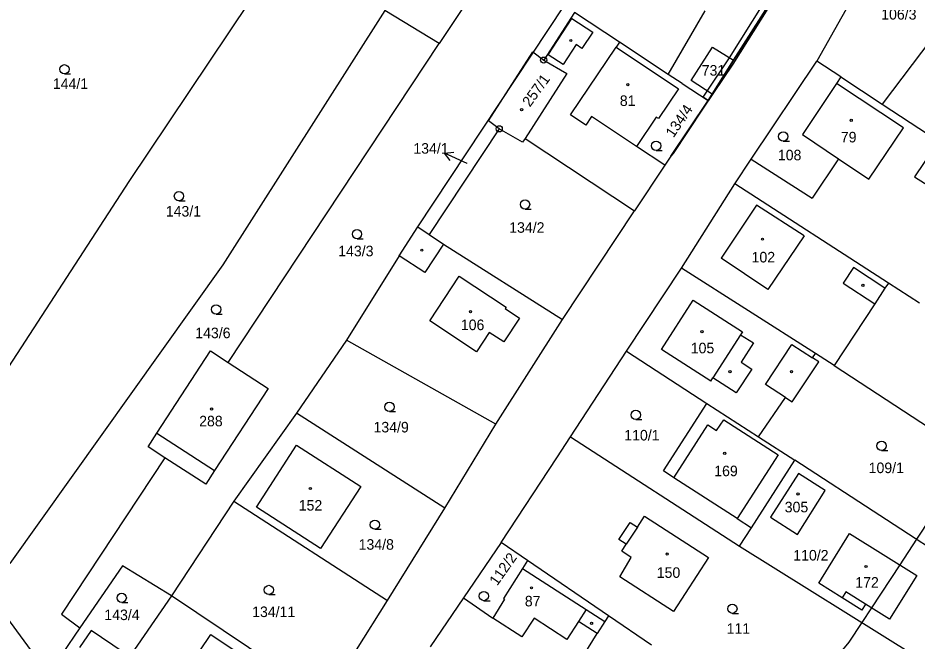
# Model space of a CAD drawing. Extents: x -747333 to -745433, y -1133152 to -1130600.
# Drawn here: x -746336.6 to -746191.7, y -1131743.1 to -1131642.6 of the extents above; entities that cross this region are included whole.
import ezdxf

# ---------------------------------------------------------------- set-up
doc = ezdxf.new("R2010")
doc.units = 0
for name, color, linetype in [('Vrstva 1', 7, 'Continuous'), ('Vrstva 16', 7, 'Continuous'), ('Vrstva 18', 7, 'Continuous'), ('Vrstva 19', 7, 'Continuous'), ('Vrstva 24', 7, 'Continuous'), ('Vrstva 25', 7, 'Continuous'), ('Vrstva 3', 7, 'Continuous'), ('Vrstva 30', 7, 'Continuous'), ('Vrstva 37', 7, 'Continuous'), ('Vrstva 4', 7, 'Continuous'), ('Vrstva 52', 7, 'Continuous'), ('Vrstva 6', 7, 'Continuous')]:
    doc.layers.add(name, color=color, linetype=linetype)

msp = doc.modelspace()

# ---------------------------------------------------------------- linework, layer by layer
at = {"layer": 'Vrstva 1'}
for p, q in [((-746246.92, -1131641.69), (-746251.87, -1131649.36)), ((-746302.76, -1131698.11), (-746268.75, -1131646.7)), ((-746251.87, -1131649.36), (-746248.14, -1131651.53)), ((-746248.14, -1131651.53), (-746254.86, -1131661.98)), ((-746259.04, -1131660.44), (-746270.36, -1131677.49)), ((-746255.27, -1131662.62), (-746259.04, -1131660.44)), ((-746254.86, -1131661.98), (-746255.27, -1131662.62)), ((-746254.86, -1131661.98), (-746237.23, -1131673.69)), ((-746314.24, -1131709.54), (-746305.6, -1131696.26)), ((-746305.6, -1131696.26), (-746302.76, -1131698.11)), ((-746208.52, -1131697.37), (-746208.05, -1131696.69)), ((-746302.76, -1131698.11), (-746296.31, -1131702.3)), ((-746211.79, -1131704.5), (-746207.53, -1131698.01)), ((-746207.53, -1131698.01), (-746208.52, -1131697.37)), ((-746296.31, -1131702.3), (-746304.95, -1131715.57)), ((-746217.23, -1131710.1), (-746212.9, -1131703.77)), ((-746212.9, -1131703.77), (-746211.79, -1131704.5)), ((-746315.66, -1131711.72), (-746314.24, -1131709.54)), ((-746312.93, -1131713.49), (-746315.66, -1131711.72)), ((-746312.93, -1131713.49), (-746329.64, -1131738.75)), ((-746306.37, -1131717.75), (-746312.93, -1131713.49)), ((-746304.95, -1131715.57), (-746306.37, -1131717.75)), ((-746210.77, -1131716.05), (-746215.29, -1131723.08)), ((-746206.49, -1131718.76), (-746210.77, -1131716.05)), ((-746210.97, -1131725.86), (-746206.49, -1131718.76)), ((-746215.29, -1131723.08), (-746210.97, -1131725.86)), ((-746324.84, -1131741.34), (-746326.74, -1131744.1)), ((-746319.67, -1131744.87), (-746324.84, -1131741.34))]:
    msp.add_line(p, q, dxfattribs=at)
for points in [[(-746256.41, -1131628.18), (-746268.75, -1131646.7)], [(-746221.25, -1131649.38), (-746209.49, -1131630.87)], [(-746178.11, -1131631.02), (-746197.29, -1131656.44)], [(-746200.96, -1131637.27), (-746207.82, -1131649.53)], [(-746277.47, -1131641.33), (-746303.62, -1131682.4)], [(-746268.75, -1131646.7), (-746277.47, -1131641.33)], [(-746272.19, -1131676.27), (-746248.59, -1131640.59)], [(-746239.66, -1131646.47), (-746246.92, -1131641.69)], [(-746231.78, -1131651.66), (-746225.82, -1131641.41)], [(-746239.66, -1131646.47), (-746240.2, -1131647.27)], [(-746240.2, -1131647.27), (-746230.15, -1131654.01)], [(-746231.78, -1131651.66), (-746239.66, -1131646.47)], [(-746228.08, -1131652.63), (-746224.65, -1131647.29)], [(-746224.65, -1131647.29), (-746221.25, -1131649.38)], [(-746259.04, -1131660.44), (-746260.76, -1131659.13), (-746253.62, -1131648.01), (-746251.87, -1131649.36)], [(-746224.73, -1131654.87), (-746221.25, -1131649.38)], [(-746218.4, -1131665.32), (-746207.82, -1131649.53)], [(-746203.97, -1131652.06), (-746207.82, -1131649.53)], [(-746229.55, -1131653.12), (-746231.78, -1131651.66)], [(-746229.55, -1131653.12), (-746225.37, -1131655.87)], [(-746224.73, -1131654.87), (-746228.08, -1131652.63)], [(-746204.68, -1131653.13), (-746210.15, -1131661.38)], [(-746203.97, -1131652.06), (-746204.68, -1131653.13)], [(-746203.97, -1131652.06), (-746197.29, -1131656.44)], [(-746230.15, -1131654.01), (-746233.36, -1131658.8)], [(-746225.37, -1131655.87), (-746224.73, -1131654.87)], [(-746225.37, -1131655.87), (-746232.33, -1131666.33)], [(-746197.29, -1131656.44), (-746178.01, -1131669.1)], [(-746233.75, -1131658.54), (-746236.91, -1131663.29)], [(-746233.36, -1131658.8), (-746233.75, -1131658.54)], [(-746210.15, -1131661.38), (-746204.34, -1131665.28)], [(-746232.33, -1131666.33), (-746236.91, -1131663.29)], [(-746232.33, -1131666.33), (-746237.23, -1131673.69)], [(-746221.07, -1131669.31), (-746218.4, -1131665.32)], [(-746218.4, -1131665.32), (-746208.6, -1131671.63)], [(-746204.34, -1131665.28), (-746208.6, -1131671.63)], [(-746229.64, -1131682.94), (-746221.07, -1131669.31)], [(-746196.29, -1131685.32), (-746221.07, -1131669.31)], [(-746248.85, -1131691.18), (-746237.23, -1131673.69)], [(-746275.18, -1131680.92), (-746272.19, -1131676.27)], [(-746272.19, -1131676.27), (-746270.36, -1131677.49)], [(-746270.36, -1131677.49), (-746268.02, -1131679.05)], [(-746268.02, -1131679.05), (-746248.85, -1131691.18)], [(-746275.18, -1131680.92), (-746283.65, -1131694.51)], [(-746303.62, -1131682.4), (-746337.96, -1131730.57)], [(-746238.54, -1131696.32), (-746229.64, -1131682.94)], [(-746208.05, -1131696.69), (-746229.64, -1131682.94)], [(-746196.29, -1131685.32), (-746196.84, -1131686.16)], [(-746191.3, -1131688.55), (-746196.29, -1131685.32)], [(-746196.84, -1131686.16), (-746198.48, -1131688.67)], [(-746198.48, -1131688.67), (-746205.01, -1131698.62)], [(-746259.58, -1131708.06), (-746248.85, -1131691.18)], [(-746283.65, -1131694.51), (-746291.7, -1131706.32)], [(-746259.58, -1131708.06), (-746283.65, -1131694.51)], [(-746247.57, -1131710.13), (-746238.54, -1131696.32)], [(-746238.54, -1131696.32), (-746225.54, -1131704.73)], [(-746205.01, -1131698.62), (-746208.05, -1131696.69)], [(-746205.01, -1131698.62), (-746175.84, -1131717.7)], [(-746232.57, -1131715.63), (-746225.54, -1131704.73)], [(-746225.54, -1131704.73), (-746217.23, -1131710.1)], [(-746291.7, -1131706.32), (-746301.83, -1131720.48)], [(-746267.83, -1131721.62), (-746291.7, -1131706.32)], [(-746267.83, -1131721.62), (-746259.58, -1131708.06)], [(-746249.77, -1131713.5), (-746247.57, -1131710.13)], [(-746247.57, -1131710.13), (-746220.28, -1131727.78)], [(-746217.23, -1131710.1), (-746211.35, -1131713.91)], [(-746298.18, -1131721.44), (-746291.72, -1131711.44)], [(-746291.72, -1131711.44), (-746281.34, -1131718.15)], [(-746258.71, -1131727.17), (-746249.77, -1131713.5)], [(-746218.35, -1131724.78), (-746211.35, -1131713.91)], [(-746183.97, -1131731.72), (-746211.35, -1131713.91)], [(-746230.88, -1131716.72), (-746232.57, -1131715.63)], [(-746220.68, -1131723.28), (-746230.88, -1131716.72)], [(-746281.34, -1131718.15), (-746287.86, -1131728.15)], [(-746301.83, -1131720.48), (-746311.89, -1131735.77)], [(-746301.83, -1131720.48), (-746277.08, -1131736.51)], [(-746287.86, -1131728.15), (-746298.18, -1131721.44)], [(-746277.08, -1131736.51), (-746267.83, -1131721.62)], [(-746236.77, -1131724.69), (-746235.61, -1131722.9)], [(-746235.61, -1131722.9), (-746225.29, -1131729.6)], [(-746239.73, -1131726.67), (-746237.95, -1131723.93)], [(-746237.95, -1131723.93), (-746236.77, -1131724.69)], [(-746220.68, -1131723.28), (-746218.35, -1131724.78)], [(-746220.28, -1131727.78), (-746218.35, -1131724.78)], [(-746207.52, -1131733.7), (-746202.54, -1131725.73)], [(-746202.54, -1131725.73), (-746191.73, -1131732.48)], [(-746258.71, -1131727.17), (-746264.78, -1131736.1)], [(-746254.46, -1131730.08), (-746258.71, -1131727.17)], [(-746238.56, -1131727.43), (-746239.73, -1131726.67)], [(-746239.28, -1131728.55), (-746238.56, -1131727.43)], [(-746237.75, -1131729.59), (-746239.28, -1131728.55)], [(-746220.28, -1131727.78), (-746191.89, -1131745.5)], [(-746254.46, -1131730.08), (-746255.26, -1131731.34)], [(-746241.4, -1131739.01), (-746254.46, -1131730.08)], [(-746239.58, -1131732.69), (-746237.75, -1131729.59)], [(-746225.29, -1131729.6), (-746230.93, -1131738.3)], [(-746319.8, -1131730.94), (-746326.66, -1131740.92)], [(-746311.89, -1131735.77), (-746319.8, -1131730.94)], [(-746255.26, -1131731.34), (-746258.34, -1131736.22)], [(-746230.93, -1131738.3), (-746239.58, -1131732.69)], [(-746191.73, -1131732.48), (-746196.12, -1131739.51)], [(-746203.72, -1131736.08), (-746207.52, -1131733.7)], [(-746311.89, -1131735.77), (-746321.79, -1131750.13)], [(-746287.07, -1131752.41), (-746311.89, -1131735.77)], [(-746287.07, -1131752.41), (-746277.08, -1131736.51)], [(-746264.78, -1131736.1), (-746270.15, -1131743.99)], [(-746264.78, -1131736.1), (-746260.09, -1131739.35)], [(-746258.18, -1131736.32), (-746260.09, -1131739.35)], [(-746258.34, -1131736.22), (-746258.18, -1131736.32)], [(-746200.56, -1131738.06), (-746203.72, -1131736.08)], [(-746199.96, -1131737.11), (-746200.56, -1131738.06)], [(-746196.12, -1131739.51), (-746199.96, -1131737.11)], [(-746329.64, -1131738.75), (-746326.66, -1131740.92)], [(-746242, -1131739.93), (-746243.25, -1131741.86)], [(-746241.4, -1131739.01), (-746242, -1131739.93)], [(-746234.47, -1131743.75), (-746241.4, -1131739.01)], [(-746326.66, -1131740.92), (-746329.53, -1131745.1)], [(-746310.74, -1131749.77), (-746305.53, -1131742.02)], [(-746305.53, -1131742.02), (-746296.31, -1131748.21)], [(-746252.15, -1131756.25), (-746243.25, -1131741.86)]]:
    msp.add_lwpolyline(points, dxfattribs=at)
at = {"layer": 'Vrstva 16'}
msp.add_line((-746266.974757, -1131665.573255), (-746267.838035, -1131664.345553), dxfattribs=at)
msp.add_lwpolyline([(-746264.21, -1131666.03), (-746267.838035, -1131664.345553), (-746266.34309, -1131664.212742)], dxfattribs=at)
at = {"layer": 'Vrstva 24'}
for p, q in [((-746251.92, -1131649.36), (-746251.82, -1131649.36)), ((-746259.09, -1131660.44), (-746258.99, -1131660.44))]:
    msp.add_line(p, q, dxfattribs=at)
for centre in [(-746251.87, -1131649.36), (-746259.04, -1131660.44)]:
    msp.add_circle(centre, 0.499289, dxfattribs=at)
at = {"layer": 'Vrstva 25'}
for p, q in [((-746329.14, -1131651.59), (-746328.14, -1131651.59)), ((-746213.24, -1131662.43), (-746212.24, -1131662.43)), ((-746233.75, -1131663.93), (-746232.75, -1131663.93)), ((-746310.68, -1131672.04), (-746309.68, -1131672.04)), ((-746254.88, -1131673.38), (-746253.88, -1131673.38)), ((-746281.97, -1131678.17), (-746280.97, -1131678.17)), ((-746304.69, -1131690.32), (-746303.69, -1131690.32)), ((-746276.75, -1131706.05), (-746275.75, -1131706.05)), ((-746237.03, -1131707.33), (-746236.03, -1131707.33)), ((-746197.39, -1131712.32), (-746196.39, -1131712.32)), ((-746279.09, -1131725.04), (-746278.09, -1131725.04)), ((-746296.19, -1131735.57), (-746295.19, -1131735.57)), ((-746319.91, -1131736.84), (-746318.91, -1131736.84)), ((-746261.52, -1131736.55), (-746260.52, -1131736.55)), ((-746221.45, -1131738.59), (-746220.45, -1131738.59))]:
    msp.add_line(p, q, dxfattribs=at)
for centre, radius in [((-746247.49, -1131646.2), 0.174503), ((-746329.14, -1131650.84), 0.75), ((-746238.31, -1131653.33), 0.174503), ((-746255.43, -1131657.35), 0.174503), ((-746202.28, -1131659.07), 0.174503), ((-746213.24, -1131661.68), 0.75), ((-746233.75, -1131663.18), 0.75), ((-746310.68, -1131671.29), 0.75), ((-746254.88, -1131672.63), 0.75), ((-746281.97, -1131677.42), 0.75), ((-746216.6, -1131678.23), 0.174503), ((-746271.51, -1131680.02), 0.174503), ((-746200.4, -1131685.69), 0.174503), ((-746304.69, -1131689.57), 0.75), ((-746263.68, -1131689.93), 0.174503), ((-746226.35, -1131693.16), 0.174503), ((-746221.83, -1131699.62), 0.174503), ((-746211.91, -1131699.61), 0.174503), ((-746305.42, -1131705.64), 0.174503), ((-746276.75, -1131705.3), 0.75), ((-746237.03, -1131706.58), 0.75), ((-746197.39, -1131711.57), 0.75), ((-746222.68, -1131712.78), 0.174503), ((-746289.49, -1131718.46), 0.174503), ((-746210.86, -1131719.34), 0.174503), ((-746279.09, -1131724.29), 0.75), ((-746231.96, -1131729.03), 0.174503), ((-746199.9, -1131731.04), 0.174503), ((-746296.19, -1131734.82), 0.75), ((-746253.84, -1131734.48), 0.174503), ((-746319.91, -1131736.09), 0.75), ((-746261.52, -1131735.8), 0.75), ((-746221.45, -1131737.84), 0.75), ((-746244.15, -1131740.21), 0.174503)]:
    msp.add_circle(centre, radius, dxfattribs=at)
at = {"layer": 'Vrstva 3'}
for points in [[(-746247.54, -1131658.2), (-746240.2, -1131647.27)], [(-746240.2, -1131647.27), (-746230.15, -1131654.01)], [(-746259.04, -1131660.44), (-746260.76, -1131659.13), (-746253.62, -1131648.01), (-746251.87, -1131649.36)], [(-746251.87, -1131649.36), (-746248.14, -1131651.53)], [(-746248.14, -1131651.53), (-746254.86, -1131661.98)], [(-746204.68, -1131653.13), (-746210.15, -1131661.38)], [(-746193.87, -1131660.27), (-746204.68, -1131653.13)], [(-746230.15, -1131654.01), (-746233.36, -1131658.8)], [(-746245.06, -1131659.85), (-746247.54, -1131658.2)], [(-746244.15, -1131658.48), (-746245.06, -1131659.85)], [(-746236.91, -1131663.29), (-746244.15, -1131658.48)], [(-746233.75, -1131658.54), (-746236.91, -1131663.29)], [(-746233.36, -1131658.8), (-746233.75, -1131658.54)], [(-746255.27, -1131662.62), (-746259.04, -1131660.44)], [(-746199.42, -1131668.58), (-746193.87, -1131660.27)], [(-746254.86, -1131661.98), (-746255.27, -1131662.62)], [(-746210.15, -1131661.38), (-746204.34, -1131665.28)], [(-746204.34, -1131665.28), (-746199.42, -1131668.58)], [(-746217.55, -1131672.77), (-746223.27, -1131681.3)], [(-746209.89, -1131677.72), (-746217.55, -1131672.77)], [(-746209.89, -1131677.72), (-746215.75, -1131686.34)], [(-746215.75, -1131686.34), (-746223.27, -1131681.3)], [(-746270.22, -1131691.39), (-746265.49, -1131684.21)], [(-746265.49, -1131684.21), (-746257.93, -1131689.19)], [(-746232.86, -1131696.03), (-746227.77, -1131688.09)], [(-746227.77, -1131688.09), (-746219.83, -1131693.18)], [(-746257.93, -1131689.19), (-746258.1, -1131689.44)], [(-746258.1, -1131689.44), (-746255.76, -1131690.98)], [(-746255.76, -1131690.98), (-746258.29, -1131694.82)], [(-746262.72, -1131696.4), (-746270.22, -1131691.39)], [(-746260.66, -1131693.3), (-746262.72, -1131696.4)], [(-746258.29, -1131694.82), (-746260.66, -1131693.3)], [(-746220.13, -1131693.65), (-746224.59, -1131700.61)], [(-746219.83, -1131693.18), (-746220.13, -1131693.65)], [(-746314.24, -1131709.54), (-746305.6, -1131696.26)], [(-746305.6, -1131696.26), (-746302.76, -1131698.11)], [(-746224.92, -1131701.12), (-746232.86, -1131696.03)], [(-746302.76, -1131698.11), (-746296.31, -1131702.3)], [(-746224.92, -1131701.12), (-746224.59, -1131700.61)], [(-746296.31, -1131702.3), (-746304.95, -1131715.57)], [(-746230.88, -1131716.72), (-746225.39, -1131708.18)], [(-746225.39, -1131708.18), (-746223.99, -1131709.08)], [(-746223.99, -1131709.08), (-746222.85, -1131707.37)], [(-746222.85, -1131707.37), (-746214.04, -1131713.03)], [(-746314.24, -1131709.54), (-746311.5, -1131711.32)], [(-746311.5, -1131711.32), (-746304.95, -1131715.57)], [(-746298.18, -1131721.44), (-746291.72, -1131711.44)], [(-746291.72, -1131711.44), (-746281.34, -1131718.15)], [(-746214.04, -1131713.03), (-746220.68, -1131723.28)], [(-746220.68, -1131723.28), (-746230.88, -1131716.72)], [(-746210.77, -1131716.05), (-746215.29, -1131723.08)], [(-746206.49, -1131718.76), (-746210.77, -1131716.05)], [(-746281.34, -1131718.15), (-746287.86, -1131728.15)], [(-746210.97, -1131725.86), (-746206.49, -1131718.76)], [(-746287.86, -1131728.15), (-746298.18, -1131721.44)], [(-746236.77, -1131724.69), (-746235.61, -1131722.9)], [(-746235.61, -1131722.9), (-746225.29, -1131729.6)], [(-746215.29, -1131723.08), (-746210.97, -1131725.86)], [(-746236.77, -1131724.69), (-746238.56, -1131727.43)], [(-746207.52, -1131733.7), (-746202.54, -1131725.73)], [(-746202.54, -1131725.73), (-746191.73, -1131732.48)], [(-746239.28, -1131728.55), (-746238.56, -1131727.43)], [(-746237.75, -1131729.59), (-746239.28, -1131728.55)], [(-746239.58, -1131732.69), (-746237.75, -1131729.59)], [(-746225.29, -1131729.6), (-746230.93, -1131738.3)], [(-746255.26, -1131731.34), (-746258.34, -1131736.22)], [(-746255.26, -1131731.34), (-746245.02, -1131737.97)], [(-746230.93, -1131738.3), (-746239.58, -1131732.69)], [(-746191.73, -1131732.48), (-746196.12, -1131739.51)], [(-746203.72, -1131736.08), (-746207.52, -1131733.7)], [(-746203.13, -1131735.12), (-746203.72, -1131736.08)], [(-746199.96, -1131737.11), (-746203.13, -1131735.12)], [(-746258.18, -1131736.32), (-746260.09, -1131739.35)], [(-746258.34, -1131736.22), (-746258.18, -1131736.32)], [(-746196.12, -1131739.51), (-746199.96, -1131737.11)], [(-746245.02, -1131737.97), (-746246.27, -1131739.9)], [(-746255.39, -1131742.39), (-746260.09, -1131739.35)], [(-746253.43, -1131739.37), (-746255.39, -1131742.39)], [(-746248.15, -1131742.8), (-746253.43, -1131739.37)], [(-746246.27, -1131739.9), (-746248.15, -1131742.8)], [(-746324.84, -1131741.34), (-746326.74, -1131744.1)], [(-746319.67, -1131744.87), (-746324.84, -1131741.34)], [(-746310.74, -1131749.77), (-746305.53, -1131742.02)], [(-746305.53, -1131742.02), (-746296.31, -1131748.21)]]:
    msp.add_lwpolyline(points, dxfattribs=at)
at = {"layer": 'Vrstva 30'}
for points in [[(-746214.18, -1131638.25), (-746221.25, -1131649.38)], [(-746221.25, -1131649.38), (-746214.18, -1131638.25)], [(-746221.92, -1131648.97), (-746216.48, -1131640.36)], [(-746215.71, -1131641.01), (-746221.38, -1131650)], [(-746225.5, -1131654.35), (-746221.92, -1131648.97)], [(-746221.38, -1131650), (-746226.15, -1131657.12)], [(-746221.25, -1131649.38), (-746224.73, -1131654.87)], [(-746224.73, -1131654.87), (-746221.25, -1131649.38)], [(-746226.17, -1131655.35), (-746225.5, -1131654.35)], [(-746224.73, -1131654.87), (-746225.37, -1131655.87)], [(-746225.37, -1131655.87), (-746224.73, -1131654.87)], [(-746226.15, -1131657.12), (-746230.97, -1131664.42), (-746231.35, -1131664.86), (-746225.37, -1131655.87)], [(-746225.37, -1131655.87), (-746226.17, -1131655.35)]]:
    msp.add_lwpolyline(points, dxfattribs=at)
at = {"layer": 'Vrstva 37'}
for centre in [(-746238.31, -1131653.33), (-746255.43, -1131657.35), (-746202.28, -1131659.07), (-746216.6, -1131678.23), (-746263.68, -1131689.93), (-746226.35, -1131693.16), (-746305.42, -1131705.64), (-746222.68, -1131712.78), (-746289.49, -1131718.46), (-746210.86, -1131719.34), (-746231.96, -1131729.03), (-746199.9, -1131731.04), (-746253.84, -1131734.48)]:
    msp.add_circle(centre, 0.174503, dxfattribs=at)
at = {"layer": 'Vrstva 4'}
for p, q in [((-746216.08, -1131701.68), (-746211.84, -1131695.22)), ((-746211.84, -1131695.22), (-746208.52, -1131697.37)), ((-746212.9, -1131703.77), (-746216.08, -1131701.68)), ((-746314.24, -1131709.54), (-746311.5, -1131711.32)), ((-746311.5, -1131711.32), (-746304.95, -1131715.57))]:
    msp.add_line(p, q, dxfattribs=at)
for points in [[(-746251.15, -1131648.49), (-746247.31, -1131642.64)], [(-746247.31, -1131642.64), (-746243.97, -1131644.83)], [(-746243.97, -1131644.83), (-746245.7, -1131647.47)], [(-746246.61, -1131646.86), (-746248.73, -1131650.08)], [(-746247.54, -1131658.2), (-746240.2, -1131647.27)], [(-746245.7, -1131647.47), (-746246.61, -1131646.86)], [(-746248.73, -1131650.08), (-746251.15, -1131648.49)], [(-746193.87, -1131660.27), (-746204.68, -1131653.13)], [(-746245.06, -1131659.85), (-746247.54, -1131658.2)], [(-746244.15, -1131658.48), (-746245.06, -1131659.85)], [(-746236.91, -1131663.29), (-746244.15, -1131658.48)], [(-746199.42, -1131668.58), (-746193.87, -1131660.27)], [(-746188.96, -1131663.55), (-746192.08, -1131668.2)], [(-746204.34, -1131665.28), (-746199.42, -1131668.58)], [(-746192.08, -1131668.2), (-746186.79, -1131671.5)], [(-746217.55, -1131672.77), (-746223.27, -1131681.3)], [(-746209.89, -1131677.72), (-746217.55, -1131672.77)], [(-746209.89, -1131677.72), (-746215.75, -1131686.34)], [(-746268.02, -1131679.05), (-746271.01, -1131683.64)], [(-746271.01, -1131683.64), (-746275.18, -1131680.92)], [(-746215.75, -1131686.34), (-746223.27, -1131681.3)], [(-746201.94, -1131682.81), (-746203.59, -1131685.32)], [(-746196.84, -1131686.16), (-746201.94, -1131682.81)], [(-746270.22, -1131691.39), (-746265.49, -1131684.21)], [(-746265.49, -1131684.21), (-746257.93, -1131689.19)], [(-746203.59, -1131685.32), (-746198.48, -1131688.67)], [(-746232.86, -1131696.03), (-746227.77, -1131688.09)], [(-746227.77, -1131688.09), (-746219.83, -1131693.18)], [(-746257.93, -1131689.19), (-746258.1, -1131689.44)], [(-746258.1, -1131689.44), (-746255.76, -1131690.98)], [(-746255.76, -1131690.98), (-746258.29, -1131694.82)], [(-746262.72, -1131696.4), (-746270.22, -1131691.39)], [(-746260.66, -1131693.3), (-746262.72, -1131696.4)], [(-746258.29, -1131694.82), (-746260.66, -1131693.3)], [(-746220.13, -1131693.65), (-746224.59, -1131700.61)], [(-746219.83, -1131693.18), (-746220.13, -1131693.65)], [(-746220.13, -1131693.65), (-746218.05, -1131694.98)], [(-746218.05, -1131694.98), (-746220.04, -1131698.08)], [(-746224.92, -1131701.12), (-746232.86, -1131696.03)], [(-746220.04, -1131698.08), (-746218.3, -1131699.2)], [(-746218.3, -1131699.2), (-746220.81, -1131703.03)], [(-746224.92, -1131701.12), (-746224.59, -1131700.61)], [(-746220.81, -1131703.03), (-746224.59, -1131700.61)], [(-746230.88, -1131716.72), (-746225.39, -1131708.18)], [(-746225.39, -1131708.18), (-746223.99, -1131709.08)], [(-746223.99, -1131709.08), (-746222.85, -1131707.37)], [(-746222.85, -1131707.37), (-746214.04, -1131713.03)], [(-746214.04, -1131713.03), (-746220.68, -1131723.28)], [(-746236.77, -1131724.69), (-746238.56, -1131727.43)], [(-746255.26, -1131731.34), (-746245.02, -1131737.97)], [(-746203.13, -1131735.12), (-746203.72, -1131736.08)], [(-746199.96, -1131737.11), (-746203.13, -1131735.12)], [(-746245.02, -1131737.97), (-746246.27, -1131739.9)], [(-746245.02, -1131737.97), (-746242, -1131739.93)], [(-746255.39, -1131742.39), (-746260.09, -1131739.35)], [(-746253.43, -1131739.37), (-746255.39, -1131742.39)], [(-746248.15, -1131742.8), (-746253.43, -1131739.37)], [(-746246.27, -1131739.9), (-746248.15, -1131742.8)], [(-746243.25, -1131741.86), (-746246.27, -1131739.9)]]:
    msp.add_lwpolyline(points, dxfattribs=at)
at = {"layer": 'Vrstva 52'}
for points in [[(-746182.85, -1131713.12), (-746191.76, -1131726.65), (-746194.47, -1131730.77), (-746199.03, -1131737.69), (-746200.59, -1131740.07), (-746202.69, -1131743.25), (-746214.09, -1131756.94), (-746216.4, -1131759.71), (-746223.94, -1131768.75), (-746227.76, -1131772.74), (-746241.74, -1131787.34), (-746242.25, -1131787.88), (-746254.44, -1131797.13), (-746268.07, -1131807.47), (-746270.75, -1131809.5)], [(-746298.31, -1131829.62), (-746296.86, -1131819.7), (-746296.69, -1131818.5), (-746296.69, -1131813.19), (-746296.69, -1131808.25), (-746297.44, -1131805.15), (-746297.94, -1131803.13), (-746298.81, -1131798.12), (-746299.85, -1131796.47), (-746301.58, -1131793.71), (-746307.58, -1131784.1), (-746310.54, -1131779.38), (-746325.41, -1131755.6), (-746328.12, -1131751.25), (-746331.52, -1131747.94), (-746333.25, -1131746.25), (-746340.87, -1131736)]]:
    msp.add_lwpolyline(points, dxfattribs=at)
at = {"layer": 'Vrstva 6'}
for points in [[(-746318.73, -1131668.93), (-746292.81, -1131630.24)], [(-746345.52, -1131710.16), (-746318.73, -1131668.93)]]:
    msp.add_lwpolyline(points, dxfattribs=at)

# ---------------------------------------------------------------- texts
at = {"layer": 'Vrstva 16'}
msp.add_text('134/1', height=1.7, dxfattribs=at).set_placement((-746272.884719, -1131664.45))
at = {"layer": 'Vrstva 18'}
for s, height, p in [('106/3', 1.7, (-746197.45, -1131642.82)), ('731', 1.7, (-746226.38881, -1131651.86)), ('144/1', 1.7, (-746331.01, -1131654.01)), ('108', 1.7, (-746214.11, -1131665.52)), ('134/1', 0.1, (-746264.21, -1131666.03)), ('143/1', 1.7, (-746312.8, -1131674.59)), ('134/2', 1.7, (-746257.43, -1131677.21)), ('143/3', 1.7, (-746285, -1131681)), ('143/6', 1.7, (-746308.05, -1131694.21)), ('134/9', 1.7, (-746279.31, -1131709.41)), ('110/1', 1.7, (-746238.88, -1131710.71)), ('109/1', 1.7, (-746199.47, -1131715.97)), ('134/8', 1.7, (-746281.71, -1131728.33)), ('110/2', 1.7, (-746211.63, -1131730.07)), ('134/11', 1.7, (-746298.88, -1131739.19)), ('143/4', 1.7, (-746322.71, -1131739.68)), ('111', 1.7, (-746222.37, -1131741.89))]:
    msp.add_text(s, height=height, dxfattribs=at).set_placement(p)
for s, rotation, p in [('134/4', 55.84032, (-746230.94, -1131661.98)), ('112/2', 54.8658, (-746259.37, -1131734.25))]:
    msp.add_text(s, height=1.7, rotation=rotation, dxfattribs=at).set_placement(p)
at = {"layer": 'Vrstva 19'}
msp.add_text('257/1', height=1.7, rotation=54, dxfattribs=at).set_placement((-746254.090511, -1131657.024316))
for s, p in [('81', (-746239.59, -1131656.75)), ('79', (-746203.96, -1131662.63)), ('102', (-746218.35, -1131681.99)), ('106', (-746265.23, -1131692.91)), ('105', (-746228.16, -1131696.65)), ('288', (-746307.421545, -1131708.43)), ('169', (-746224.37, -1131716.47)), ('152', (-746291.37, -1131722.02)), ('305', (-746213.006456, -1131722.3)), ('150', (-746233.64, -1131732.87)), ('172', (-746201.62881, -1131734.45)), ('87', (-746254.91, -1131737.47))]:
    msp.add_text(s, height=1.7, dxfattribs=at).set_placement(p)

doc.saveas('drawing.dxf')
